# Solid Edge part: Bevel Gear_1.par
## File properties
Author: Nimesh.N
Template: SEER_BevelGear.par
Last saved by: Nimesh.N
Revision: 37
Application: Solid Edge
Density: 7250.000 kg/m^3
Accuracy: 0.990
SEER_Parameters: SEERBG2#ER#1#ER#0.349065850398866#ER#1.5707963267949#ER#0.012#ER#0#ER#0#ER#1#ER#0#ER#1.2#ER#1000000#ER#1#ER#35#ER#35#ER#0.02#ER#0.02#ER#0.102#ER#0#ER#75000#ER#1000#ER#52.3598775598299#ER#104.71975511966#ER#9.54#ER#9.54#ER#0.92#ER#0#ER#0#ER#1#ER#0#ER#0#ER#1140#ER#605#ER#0#ER#1140#ER#390#ER#11#ER#SweptCutout_1#ER#Pattern_1#ER#SweptCutout_1#ER#Pattern_1#ER#D:\SolidEdgeDocs\Bevel gear 2.par#ER#0#ER#0#ER##ER##ER##ER##ER#D:\SolidEdgeDocs\Bevel gear.par#ER#D:\SolidEdgeDocs\Bevel gear 2.par
Username: Nimesh.N
Material: Iron:0.6025 , EN-GJL-250
Face Style: Gray
Fill Style: ANSI31(Iron)
Grouping: Iron\Gray Cast Iron
LibraryName: Materials-DIN
Coef. of Thermal Exp: 1.05e-05
Thermal Conductivity: 58.0
Specific Heat: 460.0
Modulus of Elasticity: 120000003072.0
Poisson's Ratio: 0.26
Yield Stress: 165593984.0
Ultimate Stress: 250000000.0
Elongation: 0.0
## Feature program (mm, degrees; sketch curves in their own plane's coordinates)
sketch for "unnamed RevolvedProtrusion 1" plane through (0, 0, 0) normal (0, 0, 1) x-axis (1, 0, 0)
  line (-32.5, -153.3241) -> (-32.5, -331.0919)
  line (-86.5, -331.0919) -> (-32.5, -331.0919)
  line (-86.5, -229.0919) -> (-86.5, -331.0919)
  line (-190.9081, -229.0919) -> (-86.5, -229.0919)
  line (-199.3934, -220.6066) -> (-190.9081, -229.0919)
  line (-218.4853, -201.5147) -> (-199.3934, -220.6066)
  line (-218.4853, -201.5147) -> (-143.4461, -132.3041)
  line (-143.4461, -132.3041) -> (-130.9114, -144.8389)
  line (-130.9114, -144.8389) -> (-122.4261, -153.3241)
  line (-122.4261, -153.3241) -> (-32.5, -153.3241)
revolve "unnamed RevolvedProtrusion 1" add finite 360 deg about sketch line (0, 111.7936) -> (0, -289.3664)
chamfer "unnamed Chamfer 1"
chamfer "Chamfer_2" setback 2
chamfer "unnamed Chamfer 2"
fillet "Round_8" radius 0.5
swept cutout "SweptCutout_1"  Profile_17_CrossSections_Plane1_Distance = 314.9848 mm; Profile_18_CrossSections_Plane2_Distance = 176.9848 mm
pattern "unnamed Pattern 1" of "SweptCutout_1"
swept cutout "unnamed SweptCutout 1"
swept cutout "unnamed SweptCutout 2"
swept cutout "unnamed SweptCutout 3"
swept cutout "unnamed SweptCutout 4"
swept cutout "unnamed SweptCutout 5"
swept cutout "unnamed SweptCutout 6"
swept cutout "unnamed SweptCutout 7"
swept cutout "unnamed SweptCutout 8"
swept cutout "unnamed SweptCutout 9"
swept cutout "unnamed SweptCutout 10"
swept cutout "unnamed SweptCutout 11"
swept cutout "unnamed SweptCutout 12"
swept cutout "unnamed SweptCutout 13"
swept cutout "unnamed SweptCutout 14"
swept cutout "unnamed SweptCutout 15"
swept cutout "unnamed SweptCutout 16"
swept cutout "unnamed SweptCutout 17"
swept cutout "unnamed SweptCutout 18"
swept cutout "unnamed SweptCutout 19"
swept cutout "unnamed SweptCutout 20"
swept cutout "unnamed SweptCutout 21"
swept cutout "unnamed SweptCutout 22"
swept cutout "unnamed SweptCutout 23"
swept cutout "unnamed SweptCutout 24"
swept cutout "unnamed SweptCutout 25"
swept cutout "unnamed SweptCutout 26"
swept cutout "unnamed SweptCutout 27"
swept cutout "unnamed SweptCutout 28"
swept cutout "unnamed SweptCutout 29"
swept cutout "unnamed SweptCutout 30"
swept cutout "unnamed SweptCutout 31"
swept cutout "unnamed SweptCutout 32"
swept cutout "unnamed SweptCutout 33"
swept cutout "unnamed SweptCutout 34"
sketch for "ExtrudedCutout_4" plane through (0, -311.3241, 0) normal (0, 1, 0) x-axis (1, 0, 0)
  circle centre (0, 0) radius 113.2801
extrude "ExtrudedCutout_4" cut finite 52 along -normal
sketch for "ExtrudedProtrusion_2" #1 plane through (0, -311.3241, 0) normal (0, 1, 0) x-axis (1, 0, 0)
  circle centre (0, 0) radius 27.5
sketch for "ExtrudedProtrusion_2" #2 plane through (0, -311.3241, 0) normal (0, 1, 0) x-axis (1, 0, 0)
  circle centre (0, 0) radius 37.5
extrude "ExtrudedProtrusion_2" add finite 158 along +normal
sketch for "ExtrudedCutout_5" plane through (0, -311.3241, 0) normal (0, 1, 0) x-axis (1, 0, 0)
  line (-9, 33) -> (9, 33)
  line (9, 33) -> (9, 0)
  line (9, 0) -> (-9, 0)
  line (-9, 0) -> (-9, 33)
  dimension (linear) = 9
extrude "ExtrudedCutout_5" cut finite 70 along +normal
sketch for "ExtrudedCutout_6" plane through (0, -311.3241, 0) normal (0, -1, 0) x-axis (-1, 0, 0)
extrude "ExtrudedCutout_6" cut finite 8.5 along -normal
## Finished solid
Body 1: sheet body, 1 face, 1 edge, 1 vertex.
  Faces by surface: cone 1
  Edges by curve: circle 1
Body 2: solid body, 224 faces, 650 edges, 428 vertices.
  Faces by surface: cone 107, spline 70, plane 42, torus 3, cylinder 2
  Edges by curve: intersection 420, circle 150, spline 70, line 10
Bounding box of the edges (mm; curved faces can reach further): 433.689 x 169.842 x 434.057, from (-216.6175, -302.8241, -217.0286) to (217.0711, -132.9821, 217.0286).
Cylindrical faces by radius (mm): R27.5 x1, R86.5 x1
Conical faces (half-angle, radius in mm at the cone's reference point): 1.1569 deg R217.0711 x35, 45 deg R130.9114 x1, 45 deg R199.3934 x1, 45 deg R210 x1, 47.3138 deg R218.4853 x35, 88.8431 deg R144.1812 x35
Toroidal faces (ring radius, tube radius in mm): R87 r0.5 x1, R122.219 r0.5 x1, R190.701 r0.5 x1
Planar faces by outward normal: +x 1, +y 1, +z 1, -x 1, -y 3, oblique 35
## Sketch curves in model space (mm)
line (0, 50.2301, 0) -> (0, -97.7151, 0)
line (-210, -210, 0) -> (0, 0, 0)
line (0, 111.7936, 0) -> (0, -289.3664, 0)
line (-126.9547, 0, 0) -> (183.7596, 0, 0)
line (0, 0, 0) -> (-199.3934, -220.6066, 0)
line (0, 0, 0) -> (-210, -210, 0)
line (0, 0, 0) -> (-218.4853, -201.5147, 0)
line (-130.9114, -144.8389, 0) -> (-122.4261, -153.3241, 0)
line (-122.4261, -153.3241, 0) -> (-32.5, -153.3241, 0)
line (-32.5, -153.3241, 0) -> (-32.5, -331.0919, 0)
line (-86.5, -331.0919, 0) -> (-32.5, -331.0919, 0)
line (-86.5, -229.0919, 0) -> (-86.5, -331.0919, 0)
line (-190.9081, -229.0919, 0) -> (-86.5, -229.0919, 0)
line (-199.3934, -220.6066, 0) -> (-190.9081, -229.0919, 0)
line (-218.4853, -201.5147, 0) -> (-199.3934, -220.6066, 0)
line (-218.4853, -201.5147, 0) -> (-143.4461, -132.3041, 0)
line (-143.4461, -132.3041, 0) -> (-130.9114, -144.8389, 0)
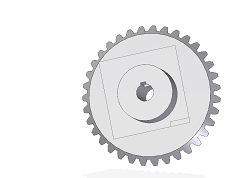
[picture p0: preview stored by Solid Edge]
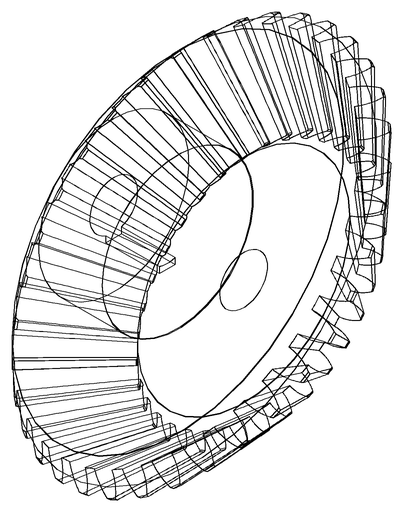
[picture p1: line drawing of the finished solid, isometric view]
